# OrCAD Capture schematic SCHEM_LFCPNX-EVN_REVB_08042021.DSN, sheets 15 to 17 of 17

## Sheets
15 Power Regulators: size C; title: Power Regulators
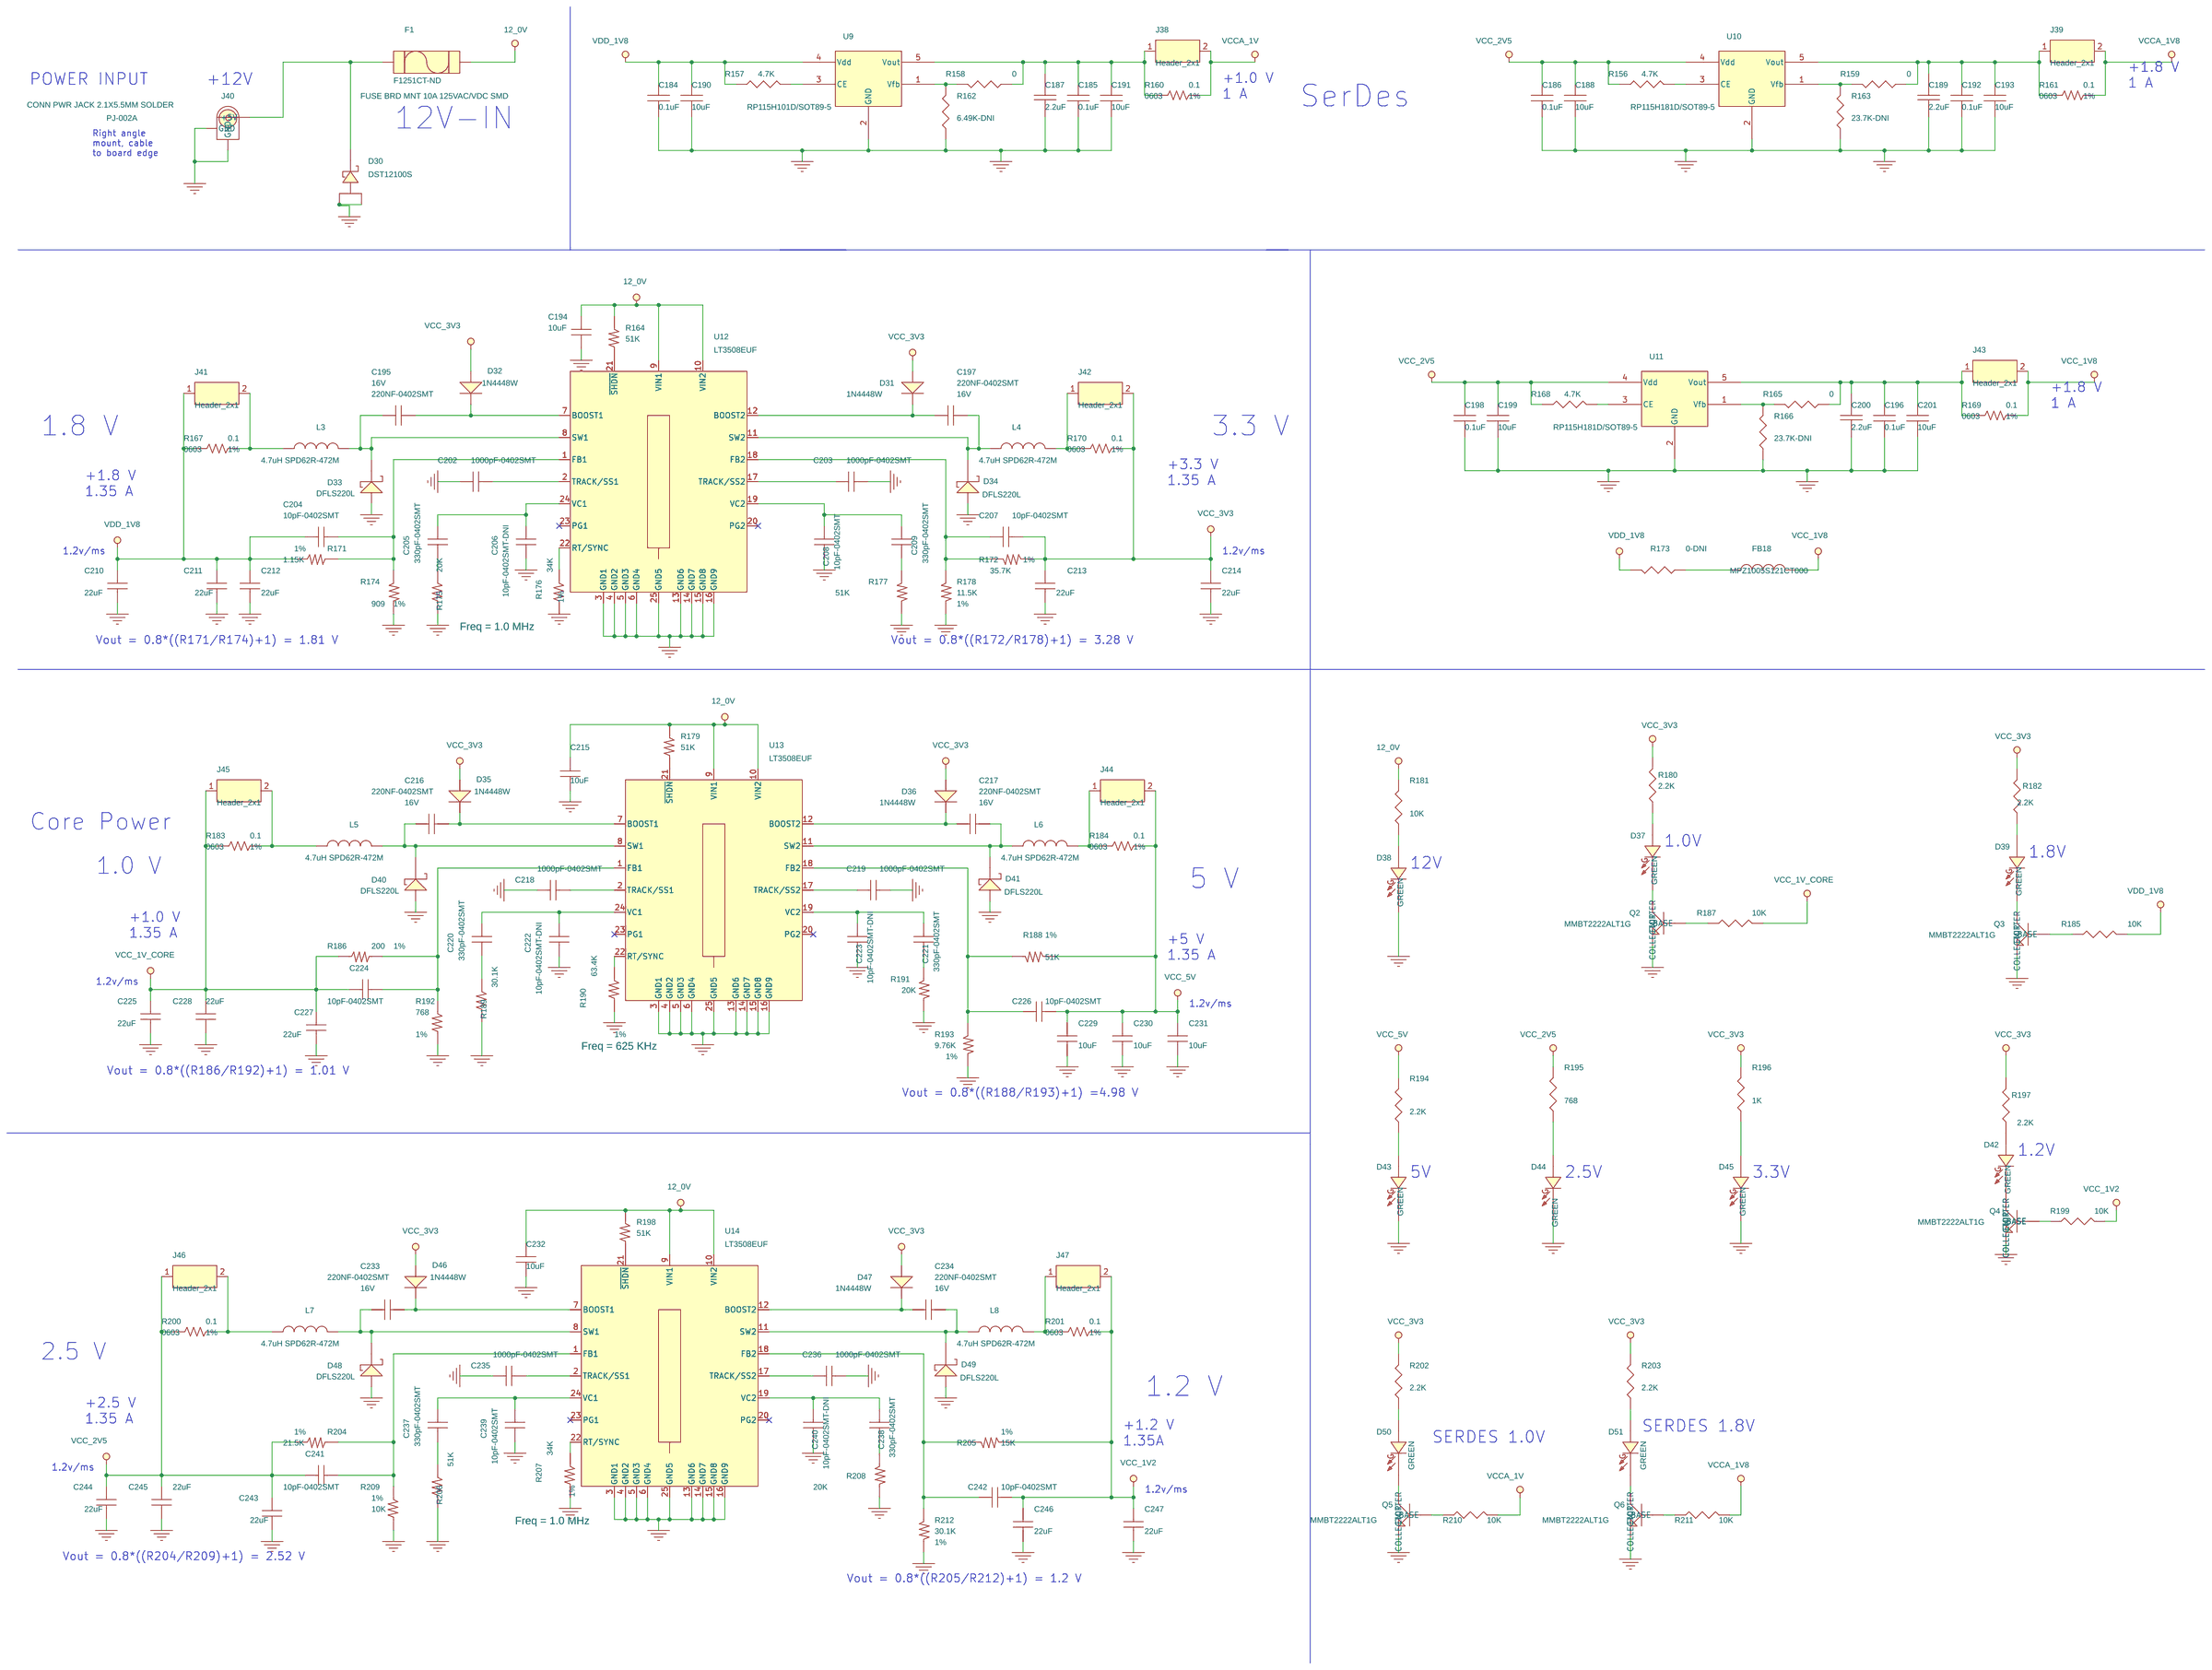
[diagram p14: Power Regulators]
16 Ground: size C; title: Ground
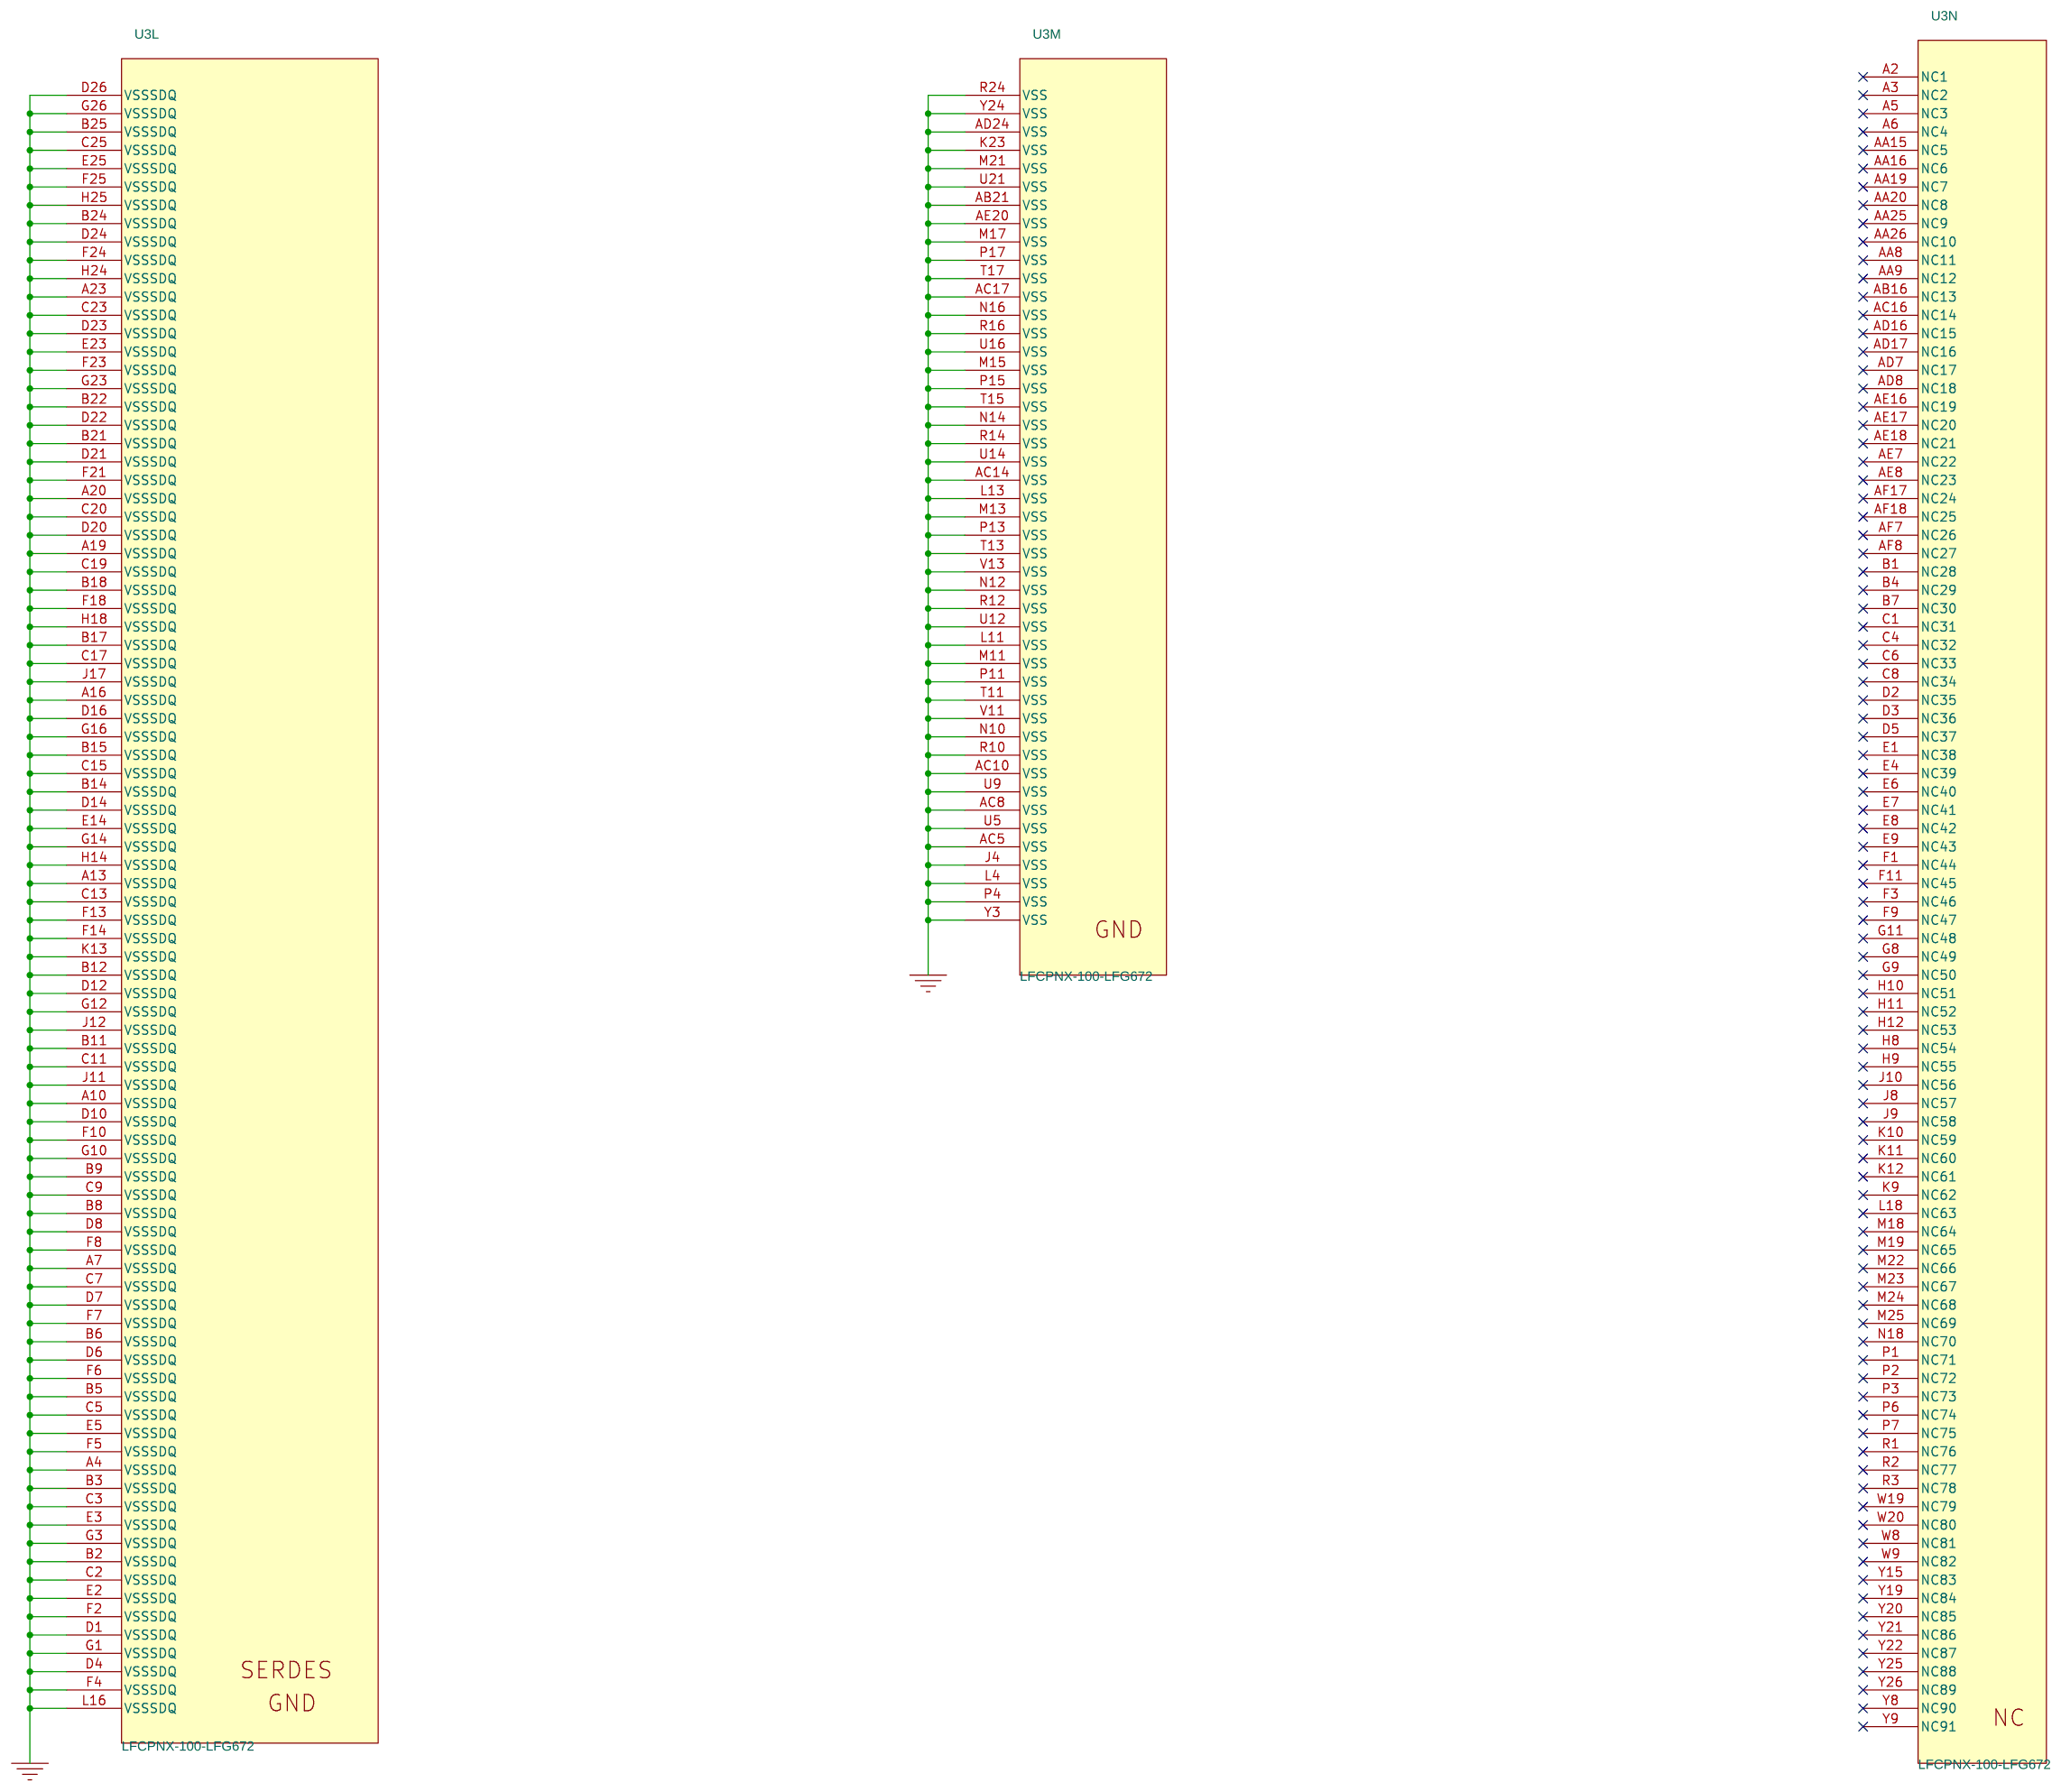
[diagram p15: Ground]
17 Power Block Diagram: title: Power Block Diagram
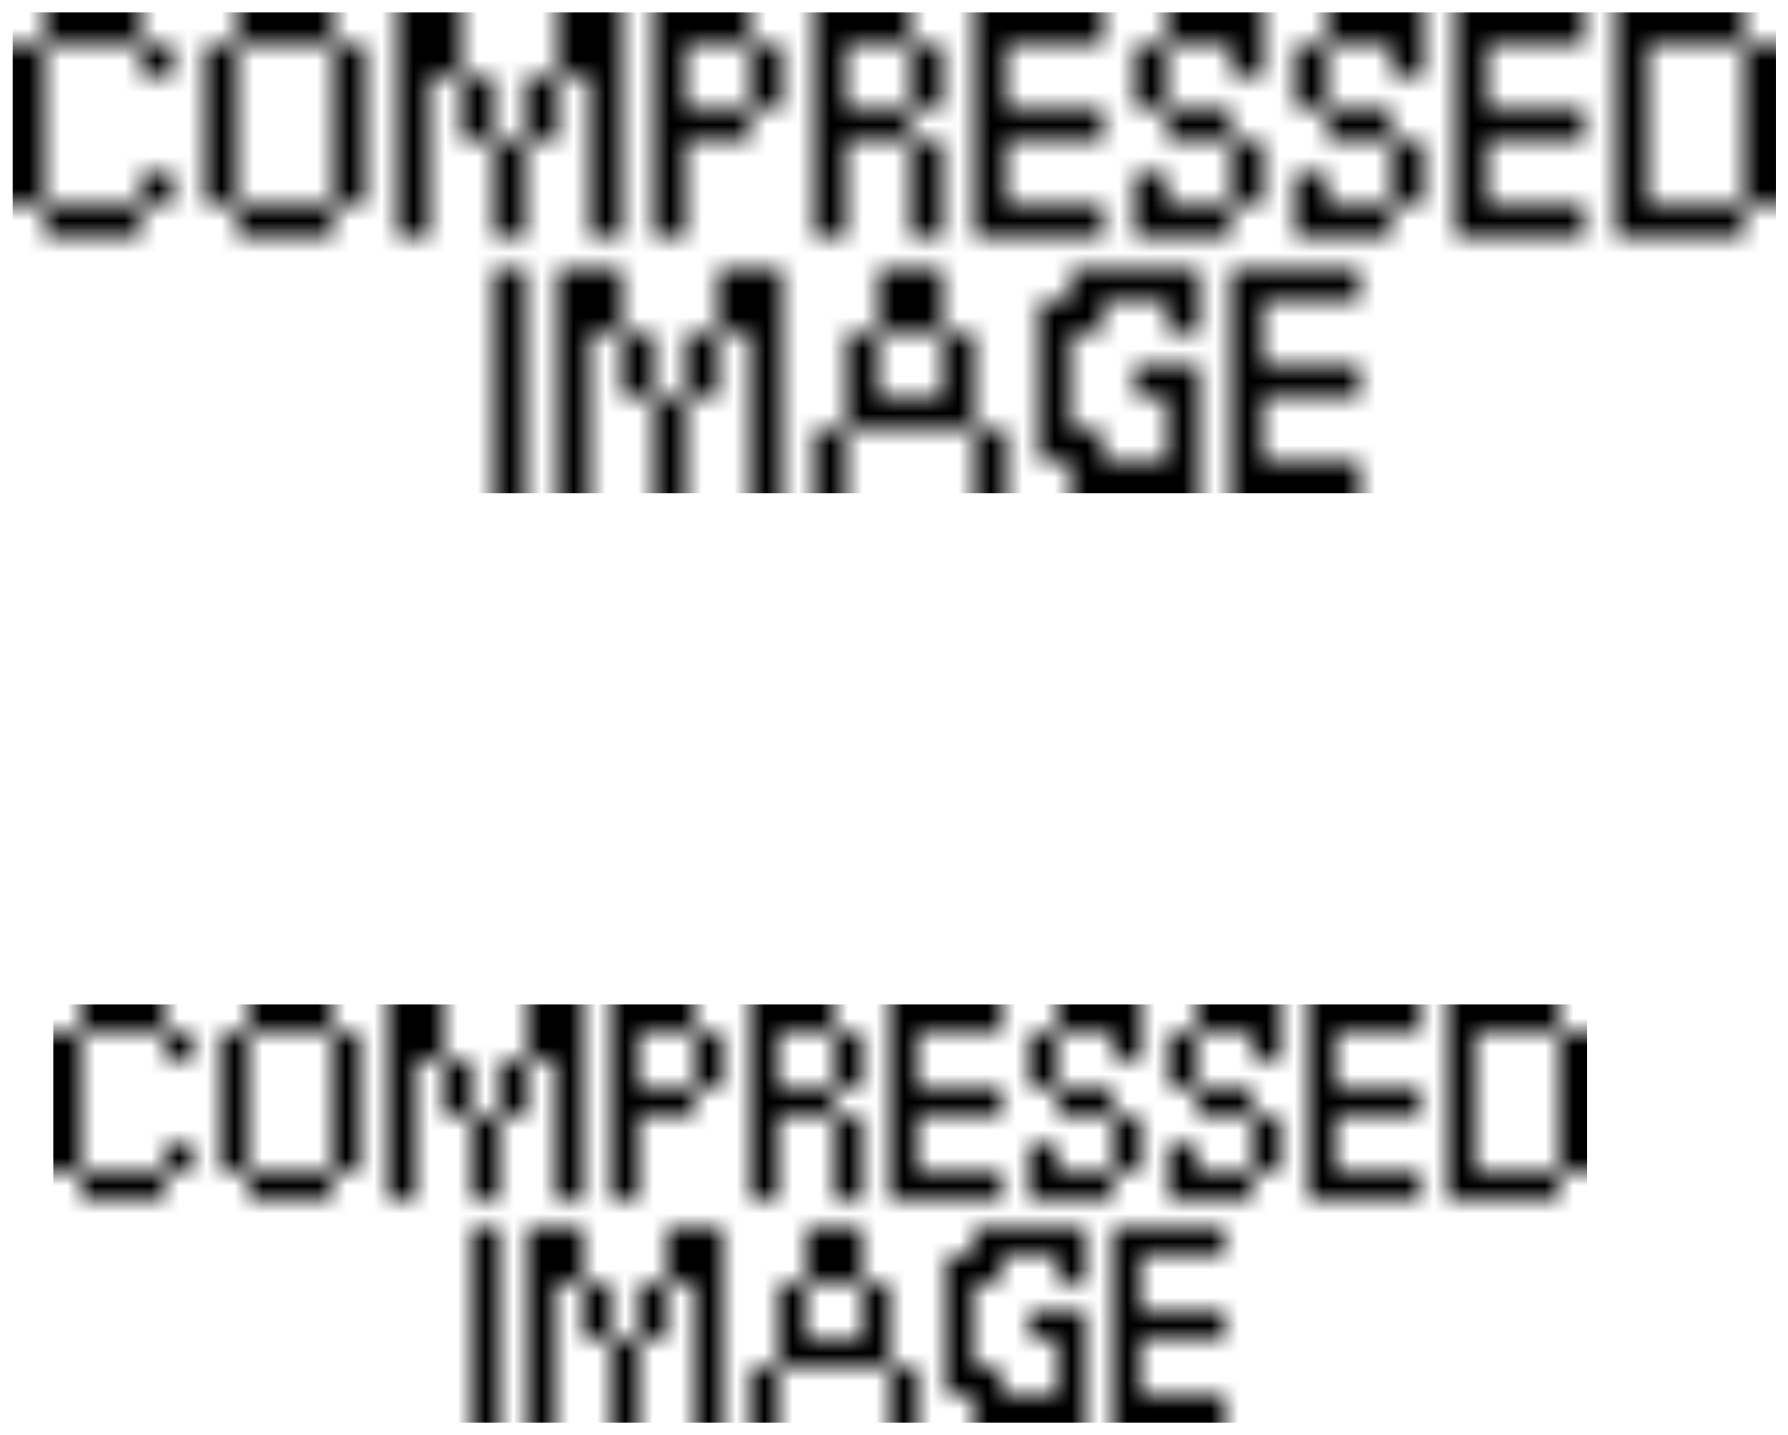
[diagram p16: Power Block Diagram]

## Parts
sheet Bank-7 Raspberry PI
U3  LFCPNX-100-LFG672  [BGA672-1P0]  (sections A,B,C,D,E,F,G,H,I,J,K,L,M,N)
sheet Power Regulators
C184  0.1uF  [C0201]
C185  0.1uF  [C0201]
C186  0.1uF  [C0201]
C187  2.2uF  [RLP-133]
C188  10uF  [C0402]
C189  2.2uF  [RLP-133]
C190  10uF  [C0402]
C191  10uF  [C0402]
C192  0.1uF  [C0201]
C193  10uF  [C0402]
C194  10uF  [C1206]
C195  220NF-0402SMT  [RLP-130-A]
C196  0.1uF  [C0201]
C197  220NF-0402SMT  [RLP-130-A]
C198  0.1uF  [C0201]
C199  10uF  [C0402]
C200  2.2uF  [RLP-133]
C201  10uF  [C0402]
C202  1000pF-0402SMT  [RLP-130-A]
C203  1000pF-0402SMT  [RLP-130-A]
C204  10pF-0402SMT  [RLP-130-A]
C205  330pF-0402SMT  [RLP-130-A]
C206  10pF-0402SMT-DNI  [RLP-130-A]
C207  10pF-0402SMT  [RLP-130-A]
C208  10pF-0402SMT  [RLP-130-A]
C209  330pF-0402SMT  [RLP-130-A]
C210  22uF  [C0603]
C211  22uF  [C0603]
C212  22uF  [C0603]
C213  22uF  [C0603]
C214  22uF  [C0603]
C215  10uF  [C1206]
C216  220NF-0402SMT  [RLP-130-A]
C217  220NF-0402SMT  [RLP-130-A]
C218  1000pF-0402SMT  [RLP-130-A]
C219  1000pF-0402SMT  [RLP-130-A]
C220  330pF-0402SMT  [RLP-130-A]
C221  330pF-0402SMT  [RLP-130-A]
C222  10pF-0402SMT-DNI  [RLP-130-A]
C223  10pF-0402SMT-DNI  [RLP-130-A]
C224  10pF-0402SMT  [RLP-130-A]
C225  22uF  [C0603]
C226  10pF-0402SMT  [RLP-130-A]
C227  22uF  [C0603]
C228  22uF  [C0603]
C229  10uF  [C1206]
C230  10uF  [C1206]
C231  10uF  [C1206]
C232  10uF  [C1206]
C233  220NF-0402SMT  [RLP-130-A]
C234  220NF-0402SMT  [RLP-130-A]
C235  1000pF-0402SMT  [RLP-130-A]
C236  1000pF-0402SMT  [RLP-130-A]
C237  330pF-0402SMT  [RLP-130-A]
C238  330pF-0402SMT  [RLP-130-A]
C239  10pF-0402SMT  [RLP-130-A]
C240  10pF-0402SMT-DNI  [RLP-130-A]
C241  10pF-0402SMT  [RLP-130-A]
C242  10pF-0402SMT  [RLP-130-A]
C243  22uF  [C0603]
C244  22uF  [C0603]
C245  22uF  [C0603]
C246  22uF  [C0603]
C247  22uF  [C0603]
D30  DST12100S  [DST12100S]
D31  1N4448W  [1N4448W]
D32  1N4448W  [1N4448W]
D33  DFLS220L  [DFLS220L]
D34  DFLS220L  [DFLS220L]
D35  1N4448W  [1N4448W]
D36  1N4448W  [1N4448W]
D37  GREEN  [APT1608]
D38  GREEN  [APT1608]
D39  GREEN  [APT1608]
D40  DFLS220L  [DFLS220L]
D41  DFLS220L  [DFLS220L]
D42  GREEN  [APT1608]
D43  GREEN  [APT1608]
D44  GREEN  [APT1608]
D45  GREEN  [APT1608]
D46  1N4448W  [1N4448W]
D47  1N4448W  [1N4448W]
D48  DFLS220L  [DFLS220L]
D49  DFLS220L  [DFLS220L]
D50  GREEN  [APT1608]
D51  GREEN  [APT1608]
F1  F1251CT-ND  [0154010]
FB18  MPZ1005S121CT000  [FB0402]
J38  Header_2x1  [Header_2x1]
J39  Header_2x1  [Header_2x1]
J40  PJ-002A  [pj_002a_3p]
J41  Header_2x1  [Header_2x1]
J42  Header_2x1  [Header_2x1]
J43  Header_2x1  [Header_2x1]
J44  Header_2x1  [Header_2x1]
J45  Header_2x1  [Header_2x1]
J46  Header_2x1  [Header_2x1]
J47  Header_2x1  [Header_2x1]
L3  4.7uH SPD62R-472M  [SPD62R]
L4  4.7uH SPD62R-472M  [SPD62R]
L5  4.7uH SPD62R-472M  [SPD62R]
L6  4.7uH SPD62R-472M  [SPD62R]
L7  4.7uH SPD62R-472M  [SPD62R]
L8  4.7uH SPD62R-472M  [SPD62R]
Q2  MMBT2222ALT1G  [MMBT2222ALT-1]
Q3  MMBT2222ALT1G  [MMBT2222ALT-1]
Q4  MMBT2222ALT1G  [MMBT2222ALT-1]
Q5  MMBT2222ALT1G  [MMBT2222ALT-1]
Q6  MMBT2222ALT1G  [MMBT2222ALT-1]
R156  4.7K  [R0603]
R157  4.7K  [R0603]
R158  0  [R0402]
R159  0  [R0402]
R160  0.1  [0603]
R161  0.1  [0603]
R162  6.49K-DNI  [R0603]
R163  23.7K-DNI  [R0603]
R164  51K  [R0402]
R165  0  [R0402]
R166  23.7K-DNI  [R0603]
R167  0.1  [0603]
R168  4.7K  [R0603]
R169  0.1  [0603]
R170  0.1  [0603]
R171  1.15K  [R0603]
R172  35.7K  [R0603]
R173  0-DNI  [R0603]
R174  909  [R0603]
R175  20K  [R0402]
R176  34K  [R0402]
R177  51K  [R0402]
R178  11.5K  [R0603]
R179  51K  [R0402]
R180  2.2K  [R1206]
R181  10K  [R1206]
R182  2.2K  [R1206]
R183  0.1  [0603]
R184  0.1  [0603]
R185  10K  [R0603]
R186  200  [R0603]
R187  10K  [R0603]
R188  51K  [R0603]
R189  30.1K  [R0402]
R190  63.4K  [R0402]
R191  20K  [R0402]
R192  768  [R0603]
R193  9.76K  [R0603]
R194  2.2K  [R1206]
R195  768  [R0603]
R196  1K  [R0603]
R197  2.2K  [R1206]
R198  51K  [R0402]
R199  10K  [R0603]
R200  0.1  [0603]
R201  0.1  [0603]
R202  2.2K  [R1206]
R203  2.2K  [R1206]
R204  21.5K  [R0603]
R205  15K  [R0603]
R206  51K  [R0402]
R207  34K  [R0402]
R208  20K  [R0402]
R209  10K  [R0603]
R210  10K  [R0603]
R211  10K  [R0603]
R212  30.1K  [R0402]
U9  RP115H101D/SOT89-5  [SOT89-5]
U10  RP115H181D/SOT89-5  [SOT89-5]
U11  RP115H181D/SOT89-5  [SOT89-5]
U12  LT3508EUF  [LT3508EUF]
U13  LT3508EUF  [LT3508EUF]
U14  LT3508EUF  [LT3508EUF]

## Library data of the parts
U3 = LFCPNX100K-FFG672
C184-C186 C192 C196 C198 = 0u1_0402: CAP CER 0.1UF 16V 10% X7R 0402
C187 C189 C200 = CAP_SMT_0805: CAP CER 2.2UF 16V X7R 0805; MAX_TEMP: 125; MFG: Samsung Electro-Mechanics; MFG P/N: CL21B225KOFNNNE; Manufacturer: Samsung Electro-Mechanics; Manufacturer Part Number: CL21B225KOFNNNE; VENDOR: Digikey; VENDOR P/N: 1276-1162-1-ND
C188 C190 C199 = 10uF_0603: CAP CER 10UF 10V 20% X5R 0603
C191 C193 C201 = 22uF_0805: CAP CER 22UF 10V 20% X5R 0805
C194 C202-C209 C215 C218-C221 C224 C226 C232 C235-C238 C241 C242 = CAP-NP
C195 C197 C216 C217 C233 C234 = CAP-NP: COMPFIXED: 16V
C210-C214 C225 C227-C231 C243-C247 = CAP-NP: CAP CER 22UF 10V X5R 0805; Manufacturer: Samsung; Manufacturer Part Number: CL21A226KPCLRNC
C222 C223 C240 = CAP-NP: ASSY: DNI; Populate: DNI
C239 = CAP-NP: Populate: DNI
D30 = DIODE_SCHOTTKY21_0: DIODE SCHOTTKY 12A 100V TO277B; MFG: Littelfuse Inc.; Manufacturer: Littelfuse Inc.; VENDOR: Digikey
D31 D32 D35 D36 D46 D47 = DIODE_0
D33 D34 D40 D41 D48 D49 = D-SCHOTTKY_0
D37-D39 D42-D45 D50 D51 = LED-SMT1206_GREEN_1
F1 = SMTFUSE_0: FUSE BRD MNT 10A 125VAC/VDC SMD; MFG: Littelfuse Inc.; MFG P/N: 0154010.DR; Manufacturer: Littelfuse Inc.; Manufacturer Part Number: 0154010.DR; VENDOR: element14; VENDOR P/N: 1817192
FB18 = INDUCTOR_1: FERRITE BEAD 120 OHM 0402 1LN; Manufacturer: TDK Corporation
J38 J39 J41-J47 = Header_2x1
J40 = 22HP037A: CONN PWR JACK 2.1X5.5MM SOLDER; MFG: Wurth Electronics Inc.; MFG P/N: 694106301002; Manufacturer: Wurth Electronics Inc.; Manufacturer Part Number: 694106301002; VENDOR: Digikey; VENDOR P/N: 732-5930-ND
L3 L5 L7 = IND: COMPFIXED: SUMIDA; COMPGROUP: CDRH3D18
L4 L6 L8 = IND: COMPFIXED: SUMIDA; COMPGROUP: CDRH3D18C
Q2 Q3 = 2N2222
Q4-Q6 = 2N2222: TRANS NPN 40V 0.6A SMD SOT23-3; MAX_TEMP: 150; MFG: Diodes Incorporated; MFG P/N: MMBT2222A-7-F; Manufacturer: Diodes Incorporated; Manufacturer Part Number: MMBT2222A-7-F; VENDOR: Digikey; VENDOR P/N: MMBT2222A-FDICT-ND
R156-R159 R162 R163 R165 R166 R168 = 5k1_0402: RES 4.70K OHM 1/10W 1% 0603 SMD; Digikey P/N: 541-4.70KHTR-ND; Manufacturer: Vishay; Manufacturer Part Number: CRCW06034K70FKEA
R160 R161 R167 R169 R170 R183 R184 R200 R201 = R_v3: COMPFIXED: NO; COMPGROUP: 0; COMPHEIGHT: 0.000; COMPKEY: NO; COMPLOC: [970.000,1160.000]; COMPLOCKED: NO; COMPROT: 180; COMPSIDE: TOP; DECOUPLER: NO; FPLIST: AX/RC05,SM/R_0603; MEMORY: NO; Tollerance: 1%
R164 R179 R198 = R_v2
R171 R172 R174 R175 R177 R178 R186 R188 R189 R191-R193 R204-R206 R208 R209 R212 = R_v2: COMPFIXED: 1%
R173 = 0R_0603: RES 0.0 OHM 1/10W JUMP 0603 SMD; Assy: DNI
R176 R207 = R_v2: COMPFIXED: 1%; COMPGROUP: Freq = 1.0 MHz
R180-R182 R194 R197 R202 R203 = RES_0: RES SMD 1.8K OHM 1% 1/4W 1206; MFG: Panasonic Electronic Components; MFG P/N: ERJ-8ENF1801V; Manufacturer Part Number: ERJ-8ENF1801V; VENDOR: Digikey; VENDOR P/N: P1.80KFCT-ND
R185 R187 R199 R210 R211 = RES_0: RES SMD 10K OHM 1% 1/10W 0402; MAX_TEMP: 155; MFG: Panasonic Electronic Components; MFG P/N: ERJ-2RKF1002X; Manufacturer Part Number: ERJ-2RKF1002X; VENDOR: Digikey; VENDOR P/N: P10.0KLCT-ND
R190 = R_v2: COMPFIXED: 1%; COMPGROUP: Freq = 625 KHz
R195 R196 = RES_0: RES SMD 220 OHM 1% 1/10W 0603; MFG: Panasonic Electronic Components; MFG P/N: ERJ-3EKF2200V; Manufacturer Part Number: ERJ-3EKF2200V; VENDOR: Digikey; VENDOR P/N: P220HCT-ND
U9-U11 = RP111HXX1D
U12-U14 = LT3508EUF-QFN24UF-4X4_0

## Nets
GND: C184.2 C185.2 C186.2 C187.2 C188.2 C189.2 C190.2 C191.2 C192.2 C193.2 C194.2 C196.2 C198.2 C199.2 C200.2 C201.2 C202.1 C203.2 C206.2 C208.2 C210.2 C211.2 C212.2 C213.2 C214.2 C215.2 C218.1 C219.2 C222.2 C223.2 C225.2 C227.2 C228.2 C229.2 C230.2 C231.2 C232.2 C235.1 C236.2 C239.2 C240.2 C243.2 C244.2 C245.2 C246.2 C247.2 D30.1(Anode1) D30.2(Anode2) D33.2 D34.2 D38.1(CATHODE) D40.2 D41.2 D43.1(CATHODE) D44.1(CATHODE) D45.1(CATHODE) D48.2 D49.2 J40.2(GND) J40.3(GND) Q2.2(EMITTER) Q3.2(EMITTER) Q4.2(EMITTER) Q5.2(EMITTER) Q6.2(EMITTER) R162.1 R163.1 R166.1 R174.2 R175.2 R176.2 R177.2 R178.2 R189.2 R190.2 R191.2 R192.2 R193.2 R206.2 R207.2 R208.2 R209.2 R212.2 U3.A4(VSSSDQ) U3.A7(VSSSDQ) U3.A10(VSSSDQ) U3.A13(VSSSDQ) U3.A16(VSSSDQ) U3.A19(VSSSDQ) U3.A20(VSSSDQ) U3.A23(VSSSDQ) U3.AB21(VSS) U3.AC5(VSS) U3.AC8(VSS) U3.AC10(VSS) U3.AC14(VSS) U3.AC17(VSS) U3.AD24(VSS) U3.AE20(VSS) U3.B2(VSSSDQ) U3.B3(VSSSDQ) U3.B5(VSSSDQ) U3.B6(VSSSDQ) U3.B8(VSSSDQ) U3.B9(VSSSDQ) U3.B11(VSSSDQ) U3.B12(VSSSDQ) U3.B14(VSSSDQ) U3.B15(VSSSDQ) U3.B17(VSSSDQ) U3.B18(VSSSDQ) U3.B21(VSSSDQ) U3.B22(VSSSDQ) U3.B24(VSSSDQ) U3.B25(VSSSDQ) U3.C2(VSSSDQ) U3.C3(VSSSDQ) U3.C5(VSSSDQ) U3.C7(VSSSDQ) U3.C9(VSSSDQ) U3.C11(VSSSDQ) U3.C13(VSSSDQ) U3.C15(VSSSDQ) U3.C17(VSSSDQ) U3.C19(VSSSDQ) U3.C20(VSSSDQ) U3.C23(VSSSDQ) U3.C25(VSSSDQ) U3.D1(VSSSDQ) U3.D4(VSSSDQ) U3.D6(VSSSDQ) U3.D7(VSSSDQ) U3.D8(VSSSDQ) U3.D10(VSSSDQ) U3.D12(VSSSDQ) U3.D14(VSSSDQ) U3.D16(VSSSDQ) U3.D20(VSSSDQ) U3.D21(VSSSDQ) U3.D22(VSSSDQ) U3.D23(VSSSDQ) U3.D24(VSSSDQ) U3.D26(VSSSDQ) U3.E2(VSSSDQ) U3.E3(VSSSDQ) U3.E5(VSSSDQ) U3.E14(VSSSDQ) U3.E23(VSSSDQ) U3.E25(VSSSDQ) U3.F2(VSSSDQ) U3.F4(VSSSDQ) U3.F5(VSSSDQ) U3.F6(VSSSDQ) U3.F7(VSSSDQ) U3.F8(VSSSDQ) U3.F10(VSSSDQ) U3.F13(VSSSDQ) U3.F14(VSSSDQ) U3.F18(VSSSDQ) U3.F21(VSSSDQ) U3.F23(VSSSDQ) U3.F24(VSSSDQ) U3.F25(VSSSDQ) U3.G1(VSSSDQ) U3.G3(VSSSDQ) U3.G10(VSSSDQ) U3.G12(VSSSDQ) U3.G14(VSSSDQ) U3.G16(VSSSDQ) U3.G23(VSSSDQ) U3.G26(VSSSDQ) U3.H14(VSSSDQ) U3.H18(VSSSDQ) U3.H24(VSSSDQ) U3.H25(VSSSDQ) U3.J4(VSS) U3.J11(VSSSDQ) U3.J12(VSSSDQ) U3.J17(VSSSDQ) U3.K13(VSSSDQ) U3.K23(VSS) U3.L4(VSS) U3.L11(VSS) U3.L13(VSS) U3.L16(VSSSDQ) U3.M11(VSS) U3.M13(VSS) U3.M15(VSS) U3.M17(VSS) U3.M21(VSS) U3.N10(VSS) U3.N12(VSS) U3.N14(VSS) U3.N16(VSS) U3.P4(VSS) U3.P11(VSS) U3.P13(VSS) U3.P15(VSS) U3.P17(VSS) U3.R10(VSS) U3.R12(VSS) U3.R14(VSS) U3.R16(VSS) U3.R24(VSS) U3.T11(VSS) U3.T13(VSS) U3.T15(VSS) U3.T17(VSS) U3.U5(VSS) U3.U9(VSS) U3.U12(VSS) U3.U14(VSS) U3.U16(VSS) U3.U21(VSS) U3.V11(VSS) U3.V13(VSS) U3.Y3(VSS) U3.Y24(VSS) U9.2(GND) U10.2(GND) U11.2(GND) U12.3(GND1) U12.4(GND2) U12.5(GND3) U12.6(GND4) U12.13(GND6) U12.14(GND7) U12.15(GND8) U12.16(GND9) U12.25(GND5) U13.3(GND1) U13.4(GND2) U13.5(GND3) U13.6(GND4) U13.13(GND6) U13.14(GND7) U13.15(GND8) U13.16(GND9) U13.25(GND5) U14.3(GND1) U14.4(GND2) U14.5(GND3) U14.6(GND4) U14.13(GND6) U14.14(GND7) U14.15(GND8) U14.16(GND9) U14.25(GND5) ; also on sheet 3 4 5 6 7 8 9 10 11 12 13 14
VCC_1V2: C242.2 C246.1 C247.1 J47.2 R199.2 R201.2 R205.1 ; also on sheet 9 13
VCC_1V8: FB18.1 J43.2 R169.2 ; also on sheet 9 13
VCC_1V_CORE: C224.1 C225.1 C227.1 C228.1 J45.1 R183.1 R186.1 R187.2 ; also on sheet 14
VCC_2V5: C186.1 C188.1 C198.1 C199.1 C241.1 C243.1 C244.1 C245.1 J46.1 R156.1 R168.1 R195.2 R200.1 R204.1 U10.4(Vdd) U11.4(Vdd) ; also on sheet 9 13
VCC_3V3: C207.2 C213.1 C214.1 D31.2 D32.2 D35.2 D36.2 D46.2 D47.2 J42.2 R170.2 R172.1 R180.2 R182.2 R196.2 R197.2 R202.2 R203.2 ; also on sheet 3 4 5 8 10 11 12 13
VCC_5V: C226.2 C229.1 C230.1 C231.1 J44.2 R184.2 R188.1 R194.2 ; also on sheet 9 10
VCCA_1V: J38.2 R160.2 R210.2 ; also on sheet 11
VCCA_1V8: J39.2 R161.2 R211.2 ; also on sheet 11 12 14
VDD_1V8: C184.1 C190.1 C204.1 C210.1 C211.1 C212.1 J41.1 R157.1 R167.1 R171.1 R173.2 R185.2 U9.4(Vdd)
12_0V: C194.1 C215.1 C232.1 F1.2 R164.1 R179.1 R181.2 R198.1 U12.9(VIN1) U12.10(VIN2) U13.9(VIN1) U13.10(VIN2) U14.9(VIN1) U14.10(VIN2) ; also on sheet 8
N17075854: J41.2 L3.1 R167.2
N17075864: C209.2 R177.1
N17075866: C208.1 C209.1 U12.19(VC2)
N17075880: C207.1 R172.2 R178.1 U12.18(FB2)
N17075896: J42.1 L4.1 R170.1
N17075942: C197.2 D34.1 L4.2 U12.11(SW2)
N17076139: R176.1 U12.22(RT/SYNC)
N17076167: C197.1 D31.1 U12.12(BOOST2)
N17076187: C203.1 U12.17(TRACK/SS2)
N17076206: C204.2 R171.2 R174.1 U12.1(FB1)
N17076208: C195.1 D33.1 L3.2 U12.8(SW1)
N17076267: C205.1 C206.1 U12.24(VC1)
N17076279: C205.2 R175.1
N17076283: C195.2 D32.1 U12.7(BOOST1)
N17076342: C202.2 U12.2(TRACK/SS1)
N17078978: J45.2 L5.1 R183.2
N17078984: C217.2 D41.1 L6.2 U13.11(SW2)
N17078989: C224.2 R186.2 R192.1 U13.1(FB1)
N17079013: C226.1 R188.2 R193.1 U13.18(FB2)
N17079015: C217.1 D36.1 U13.12(BOOST2)
N17079060: C220.1 C222.1 U13.24(VC1)
N17079075: C220.2 R189.1
N17079092: C221.2 R191.1
N17079096: C216.2 D35.1 U13.7(BOOST1)
N17079109: C216.1 D40.1 L5.2 U13.8(SW1)
N17079126: C221.1 C223.1 U13.19(VC2)
N17079253: C218.2 U13.2(TRACK/SS1)
N17079439: R190.1 U13.22(RT/SYNC)
N17079459: C219.1 U13.17(TRACK/SS2)
N17079480: J44.1 L6.1 R184.1
N17883183: D30.3(K) F1.1 J40.1(+5V)
N17884402: J47.1 L8.1 R201.1
N17884406: J46.2 L7.1 R200.2
N17884422: C234.2 D49.1 L8.2 U14.11(SW2)
N17884424: C241.2 R204.2 R209.1 U14.1(FB1)
N17884445: C242.1 R205.2 R212.1 U14.18(FB2)
N17884447: C234.1 D47.1 U14.12(BOOST2)
N17884494: C237.1 C239.1 U14.24(VC1)
N17884506: C237.2 R206.1
N17884523: C238.2 R208.1
N17884527: C233.2 D46.1 U14.7(BOOST1)
N17884534: C233.1 D48.1 L7.2 U14.8(SW1)
N17884560: C238.1 C240.1 U14.19(VC2)
N17884683: C235.2 U14.2(TRACK/SS1)
N17884869: R207.1 U14.22(RT/SYNC)
N17884887: C236.1 U14.17(TRACK/SS2)
N18086129: C185.1 C187.1 C191.1 J38.1 R158.1 R160.1 U9.5(Vout)
N18087889: C189.1 C192.1 C193.1 J39.1 R159.1 R161.1 U10.5(Vout)
N18116220: R158.2 R162.2 U9.1(Vfb)
N18117119: R156.2 U10.3(CE)
N18117122: R157.2 U9.3(CE)
N18120300: R159.2 R163.2 U10.1(Vfb)
N18528222: D50.2(ANODE) R202.1
N18528232: D50.1(CATHODE) Q5.3(COLLECTOR)
N18528255: D51.2(ANODE) R203.1
N18528265: D51.1(CATHODE) Q6.3(COLLECTOR)
N19411630: Q4.1(BASE) R199.1
N19411692: Q5.1(BASE) R210.1
N19412204: Q6.1(BASE) R211.1
N19413545: D44.2(ANODE) R195.1
N19413546: D45.2(ANODE) R196.1
N19578727: D38.2(ANODE) R181.1
N19986670: FB18.2 R173.1
N19986700: C196.1 C200.1 C201.1 J43.1 R165.1 R169.1 U11.5(Vout)
N19986854: R168.2 U11.3(CE)
N19986882: R165.2 R166.2 U11.1(Vfb)
N19991294: Q2.1(BASE) R187.1
N19991296: Q3.1(BASE) R185.1
N19991309: D37.1(CATHODE) Q2.3(COLLECTOR)
N19991313: D37.2(ANODE) R180.1
N19991328: D39.1(CATHODE) Q3.3(COLLECTOR)
N19991330: D39.2(ANODE) R182.1
N19992282: D43.2(ANODE) R194.1
N20709687: D42.1(CATHODE) Q4.3(COLLECTOR)
N20709688: R198.2 U14.21(~{SHDN})
N20709689: R179.2 U13.21(~{SHDN})
N20709690: D42.2(ANODE) R197.1
N20709691: R164.2 U12.21(~{SHDN})

Not connected (* = marked no-connect by the designer): U3 A2(NC1)* A3(NC2)* A5(NC3)* A6(NC4)* AA8(NC11)* AA9(NC12)* AA15(NC5)* AA16(NC6)* AA19(NC7)* AA20(NC8)* AA25(NC9)* AA26(NC10)* AB16(NC13)* AC16(NC14)* AD7(NC17)* AD8(NC18)* AD16(NC15)* AD17(NC16)* AE7(NC22)* AE8(NC23)* AE16(NC19)* AE17(NC20)* AE18(NC21)* AF7(NC26)* AF8(NC27)* AF17(NC24)* AF18(NC25)* B1(NC28)* B4(NC29)* B7(NC30)* C1(NC31)* C4(NC32)* C6(NC33)* C8(NC34)* D2(NC35)* D3(NC36)* D5(NC37)* E1(NC38)* E4(NC39)* E6(NC40)* E7(NC41)* E8(NC42)* E9(NC43)* F1(NC44)* F3(NC46)* F9(NC47)* F11(NC45)* G8(NC49)* G9(NC50)* G11(NC48)* H8(NC54)* H9(NC55)* H10(NC51)* H11(NC52)* H12(NC53)* J8(NC57)* J9(NC58)* J10(NC56)* K9(NC62)* K10(NC59)* K11(NC60)* K12(NC61)* L18(NC63)* M18(NC64)* M19(NC65)* M22(NC66)* M23(NC67)* M24(NC68)* M25(NC69)* N18(NC70)* P1(NC71)* P2(NC72)* P3(NC73)* P6(NC74)* P7(NC75)* R1(NC76)* R2(NC77)* R3(NC78)* W8(NC81)* W9(NC82)* W19(NC79)* W20(NC80)* Y8(NC90)* Y9(NC91)* Y15(NC83)* Y19(NC84)* Y20(NC85)* Y21(NC86)* Y22(NC87)* Y25(NC88)* Y26(NC89)*; U12 20(PG2)* 23(PG1)*; U13 20(PG2)* 23(PG1)*; U14 20(PG2)* 23(PG1)*

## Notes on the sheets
sheet 15
- +1.8 V
  1 A
- POWER INPUT
- +12V
- +1.0 V
  1 A
- SerDes
- 12V-IN
- Right angle
  mount, cable
  to board edge
- +1.8 V
  1 A
- 1.8 V
- 3.3 V
- +3.3 V
  1.35 A
- +1.8 V
  1.35 A
- 1.2v/ms
- 1.2v/ms
- Vout = 0.8*((R171/R174)+1) = 1.81 V
- Vout = 0.8*((R172/R178)+1) = 3.28 V
- Core Power
- 1.0V
- 1.8V
- 1.0 V
- 12V
- 5 V
- +1.0 V
  1.35 A
- +5 V
  1.35 A
- 1.2v/ms
- 1.2v/ms
- Vout = 0.8*((R186/R192)+1) = 1.01 V
- Vout = 0.8*((R188/R193)+1) =4.98 V
- 1.2V
- 5V
- 2.5V
- 3.3V
- 2.5 V
- 1.2 V
- +2.5 V
  1.35 A
- +1.2 V
  1.35A
- SERDES 1.8V
- SERDES 1.0V
- 1.2v/ms
- 1.2v/ms
- Vout = 0.8*((R204/R209)+1) = 2.52 V
- Vout = 0.8*((R205/R212)+1) = 1.2 V
